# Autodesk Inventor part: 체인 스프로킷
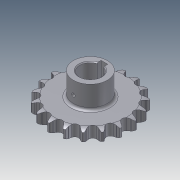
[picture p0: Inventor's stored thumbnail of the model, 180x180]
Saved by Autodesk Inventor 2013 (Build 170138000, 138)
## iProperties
Created: 2014-07
Part Number: 체인 스프로킷
Material: 강철
Document SubType Name: Modeling
Designer: KYOUNG IL JANG
Density: 7.85 g/cm^3
Mass: 738.626 g
Surface Area: 236.854 cm^2
Volume: 94.0925 cm^3
CustomPartVersion: 1
Company: 한국ATC센터
Author: KYOUNG IL JANG
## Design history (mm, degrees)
sketch "이론적 톱니 프로파일"
  geometry: L1 (0, 0)-(0, 45.567); L2 (0, 0)-(14.795, 43.098); L3 (0, 45.567)-(14.795, 43.098); L4 (0, 45.567)-(5.661, 50.015); L5 (5.661, 50.015)-(-5.141, 45.406); L6 (-12.428, 43.493)-(-5.573, 46.417); L7 (-5.141, 45.406)-(-5.573, 46.417); L8 (5.573, 46.417)-(5.141, 45.406); L9 (0, 0)-(8.138, 48.771); A1 r 45.567 centre (0, 0) between (0, 45.567) and (14.795, 43.098); A2 r 49.445 centre (0, 0) between (7.302, 48.903) and (-7.302, 48.903); A3 r 4.545 centre (0, 45.567) between (-3.574, 42.758) and (3.574, 42.758); A4 r 7.453 centre (12.428, 43.493) between (7.302, 48.903) and (5.573, 46.417); A5 r 7.453 centre (-12.428, 43.493) between (-5.573, 46.417) and (-7.302, 48.903); A6 r 11.745 centre (5.661, 50.015) between (-5.141, 45.406) and (-3.574, 42.758); A7 r 11.745 centre (-5.661, 50.015) between (3.574, 42.758) and (5.141, 45.406); 2 further points
  constraints: 18 end point, 15 point on circle, 7 centre point, 3 coincident, 3 point on line, 3 symmetric about line, 3 tangent, 1 equal radius, 1 midpoint, 1 parallel, 1 vertical, 1 other
  dimensions: "d0" = 91.13301 diameter of A1 (computed from da_p, da_z); "d2" = 18.9474 deg angle of L2 L1 (computed from da_z); "d3" = 4.545 radius of A3 (= 0.5 x da_Dr + da_SC); "d10" = 128.158 deg angle of L4 L1 (computed from da_z); "d11" = 15.0526 deg angle of L5 L4 (computed from da_z); "d12" = 7.2 distance of L3.start L4.end (= 0.8 x da_Dr); "d13" = 11.745 distance of L4.end L5.end (= 1.3 x da_Dr + da_SC); "d14" = 12.6 distance of A4.centre L1.end (= 1.4 x da_Dr); "d23" = 4.5 distance from line of L9.end L3 (= da_Ha)
sketch "톱니 프로파일"
  geometry: L1 (0, 0)-(0, 45.567); L2 (0, 45.567)-(4.203, 43.837); L3 (0, 45.567)-(-4.203, 43.837); A1 r 4.545 centre (0, 45.567) between (-4.203, 43.837) and (4.203, 43.837); A2 r 22.68 centre (25.176, 35.206) between (7.12, 48.93) and (4.203, 43.837); A3 r 22.68 centre (-25.176, 35.206) between (-4.203, 43.837) and (-7.12, 48.93); A4 r 49.445 centre (0, 0) between (-7.12, 48.93) and (7.12, 48.93) reference; 1 further point
  constraints: 9 point on circle, 6 end point, 3 centre point, 2 tangent, 1 coincident, 1 equal radius, 1 vertical, 1 other
  dimensions: "d44" = 135.263 deg angle of L3 L2 (= da_Alfa); "d45" = 22.68 radius of A2 (= da_Re); "d46" = 4.545 radius of A1 (= da_Ri)
sketch "단면 프로파일"
  geometry: L1 (49.445, 0)-(-49.445, 0) reference; L2 (33.265, 6.65)-(-33.265, 6.65); L3 (-33.265, 6.65)-(-33.265, -6.65); L4 (-33.265, -6.65)-(33.265, -6.65); L5 (33.265, -6.65)-(33.265, 6.65); L6 (33.265, 6.65)-(49.445, 6.65); L7 (49.445, 6.65)-(49.445, -6.65); L8 (49.445, -6.65)-(33.265, -6.65); L9 (33.265, -6.65)-(33.265, 6.65); L10 (42.183, 6.65)-(0, 6.65); L11 (0, 6.65)-(0, -6.65); L12 (0, -6.65)-(42.183, -6.65); L13 (0, 6.65)-(0, -6.65); L14 (49.445, 4.775)-(49.445, -4.775); A1 r 15 centre (42.183, -8.35) between (49.445, 4.775) and (42.183, 6.65); A2 r 15 centre (42.183, 8.35) between (42.183, -6.65) and (49.445, -4.775); 2 further points
  constraints: 26 end point, 7 midpoint, 5 perpendicular, 4 parallel, 4 point on circle, 3 point on line, 3 symmetric about line, 2 centre point, 2 horizontal, 2 tangent, 1 collinear, 1 other
  dimensions: "d30" = 13.3 distance between parallel lines of L8 L6 (= da_Bf); "d31" = 66.53007 distance between parallel lines of L3 L5 (= da_Ds); "d32" = 13.3 distance between parallel lines of L4 L2 (= da_Bs); "d33" = 1.875 distance from line of L14.start L6 (= da_Ba); "d34" = 15 radius of A1 (= da_Rx); "d43" = 6.65 distance between parallel lines of L4 L1 (computed from da_k, da_pt, da_Bs)
revolve "슈라우드" stored, may be unused: angle "d36" = 90 deg
revolve "스트랜드" stored, may be unused: angle "d37" = 90 deg
extrude "이론적 톱니" cut sketch "이론적 톱니 프로파일" stored distance "d18" = 10; taper "d19" = 0 deg; dims "d49" = 0, "form_type" = 0 [user parameter]
extrude "톱니" cut sketch "톱니 프로파일" stored distance "d47" = 10; taper "d48" = 0 deg; dims "d50" = 10, "form_type" = 0 [user parameter]
node "타이밍 평면"
node "작업 평면3"
sketch "스케치5"
  geometry: C1 r 20 at (0, -45.567); 1 further point
  constraints: 1 centre point, 1 coincident
  dimensions: "d52" = 40 diameter of C1
extrude "돌출4" join sketch "스케치5" stored distance "d53" = 10; taper "d54" = 0 deg
sketch "스케치6"
  geometry: L1 (4, 11.843)-(4, 16.5); L2 (4, 16.5)-(-4, 16.5); L3 (-4, 16.5)-(-4, 11.843); A1 r 12.5 centre (0, 0) between (4, 11.843) and (-4, 11.843); 1 further point
  constraints: 6 end point, 2 parallel, 2 point on circle, 1 centre point, 1 coincident, 1 perpendicular, 1 vertical
  dimensions: "d55" = 25 diameter of A1; "d56" = 29 dimension on A1 L2 (computed from d55); "d57" = 8 distance of L1.end L2.end
extrude "돌출5" cut sketch "스케치6" stored distance "d58" = 10; taper "d59" = 0 deg
fillet "모깎기2" dims "d60" = 3
chamfer "모따기1" distance "d61" = 1; stored, may be unused: second distance "d62" = 2, angle "d63" = 45 deg
node "작업 평면4"
sketch "스케치7"
  geometry: L1 (-13.5, -13.3)-(13.5, -13.3) reference; 4 further points
  constraints: 1 vertical alignment
  dimensions: "d65" = 25 distance from line of point (0, 11.7) L1
hole "구멍1" sketch "스케치7" at (0, 11.7) diameter "d66" = 4.134; stored, may be unused: countersink angle "d70" = 90 deg, drill point angle "d72" = 118 deg; dims "d67" = 6, "d68" = 4, "d69" = 2, "d71" = 8
body "Solid1"
pattern_linear "스트랜드 패턴" dims "d40" = 24 (= da_pt)
pattern_circular "톱니 패턴" dims angle "d21" = 360 deg
other parameters: "da_p" = 15 [user parameter; used in 1 equation term], "da_Dr" = 9 [user parameter; used in 4 equation terms], "da_SC" = 0.045 [user parameter; used in 2 equation terms], "da_Ha" = 4.5 [user parameter; used in 1 equation term], "da_pt" = 24 [user parameter; used in 2 equation terms], "da_Bf" = 13.3 [user parameter; used in 1 equation term], "d28" = 0, "d29" = 0, "da_Ba" = 1.875 [user parameter; used in 1 equation term], "da_Rx" = 15 [user parameter; used in 1 equation term], "da_Ra" = 0.6 [user parameter], "da_Bs" = 13.3 [user parameter; used in 2 equation terms], "da_Ds" = 66.53007 [user parameter; used in 1 equation term], "d42" = 0, "da_Re" = 22.68 [user parameter; used in 1 equation term], "da_Ri" = 4.545 [user parameter; used in 1 equation term], "da_Alfa" = 135.263 deg [user parameter; used in 1 equation term]
